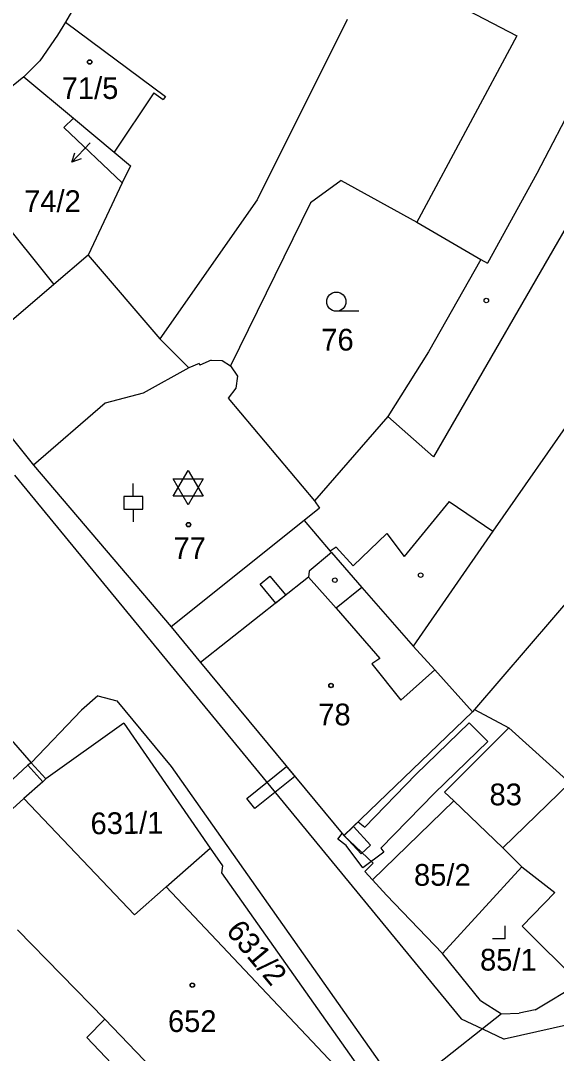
# Model space of a CAD drawing. Extents: x -593183 to -588034, y -1130415 to -1124994.
# Drawn here: x -591020.9 to -590979, y -1128867.8 to -1128787.1 of the extents above; entities that cross this region are included whole.
import ezdxf

# ---------------------------------------------------------------- set-up
doc = ezdxf.new("R2010")
doc.units = 0
for name, color, linetype in [('Vrstva 1', 7, 'Continuous'), ('Vrstva 16', 7, 'Continuous'), ('Vrstva 18', 7, 'Continuous'), ('Vrstva 19', 7, 'Continuous'), ('Vrstva 25', 7, 'Continuous'), ('Vrstva 27', 7, 'Continuous'), ('Vrstva 4', 7, 'Continuous')]:
    doc.layers.add(name, color=color, linetype=linetype)

msp = doc.modelspace()

# ---------------------------------------------------------------- linework, layer by layer
at = {"layer": 'Vrstva 1'}
for p, q in [((-591015.91, -1128784.7), (-591017.38, -1128787.22)), ((-590995.37, -1128787), (-591002.4, -1128801.12)), ((-591017.38, -1128787.22), (-591017.98, -1128788.24)), ((-591017.38, -1128787.22), (-591009.56, -1128793.02)), ((-591017.98, -1128788.24), (-591019.36, -1128790.24)), ((-591019.36, -1128790.24), (-591020.62, -1128791.5)), ((-591020.62, -1128791.5), (-591021.87, -1128792.5)), ((-591020.62, -1128791.5), (-591016.74, -1128794.73)), ((-591010.46, -1128792.73), (-591013.57, -1128797.37)), ((-591010.46, -1128792.73), (-591009.74, -1128793.26)), ((-591009.56, -1128793.02), (-591009.74, -1128793.26)), ((-590977.38, -1128793.01), (-590980.55, -1128799.05)), ((-591016.74, -1128794.73), (-591017.5, -1128795.46)), ((-591016.74, -1128794.73), (-591013.57, -1128797.37)), ((-591017.5, -1128795.46), (-591012.93, -1128799.79)), ((-591013.57, -1128797.37), (-591012.28, -1128798.44)), ((-591012.28, -1128798.44), (-591012.93, -1128799.79)), ((-590980.55, -1128799.05), (-590984.41, -1128806.07)), ((-591012.93, -1128799.79), (-591015.59, -1128805.43)), ((-590995.82, -1128799.59), (-590998.23, -1128801.33)), ((-590995.82, -1128799.59), (-590989.91, -1128802.86)), ((-591002.4, -1128801.12), (-591010.01, -1128811.97)), ((-590998.23, -1128801.33), (-591004.47, -1128814.08)), ((-590989.91, -1128802.86), (-590984.93, -1128805.77)), ((-591015.59, -1128805.43), (-591018.28, -1128807.73)), ((-591015.59, -1128805.43), (-591010.01, -1128811.97)), ((-590984.93, -1128805.77), (-590989.01, -1128812.99)), ((-590984.93, -1128805.77), (-590984.41, -1128806.07)), ((-591018.28, -1128807.73), (-591025.8, -1128814.14)), ((-591010.01, -1128811.97), (-591007.72, -1128814.25)), ((-591005.99, -1128813.64), (-591006.87, -1128814.03)), ((-591005.99, -1128813.64), (-591005.13, -1128813.68)), ((-591005.13, -1128813.68), (-591004.47, -1128814.08)), ((-590989.01, -1128812.99), (-590992.19, -1128818.04)), ((-591007.72, -1128814.25), (-591011.3, -1128816.23)), ((-591006.92, -1128813.91), (-591007.72, -1128814.25)), ((-591006.92, -1128813.91), (-591006.87, -1128814.03)), ((-591004.47, -1128814.08), (-591003.94, -1128814.88)), ((-591003.94, -1128814.88), (-591004.05, -1128815.83)), ((-591004.05, -1128815.83), (-591004.65, -1128816.6)), ((-591011.3, -1128816.23), (-591014.27, -1128817)), ((-591004.65, -1128816.6), (-590997.92, -1128824.64)), ((-591014.27, -1128817), (-591019.87, -1128821.86)), ((-590992.19, -1128818.04), (-590997.92, -1128824.64)), ((-591019.87, -1128821.86), (-591009.11, -1128834.48)), ((-590997.92, -1128824.64), (-590997.52, -1128825.22)), ((-590997.52, -1128825.22), (-590998.72, -1128826.18)), ((-590998.72, -1128826.18), (-591009.11, -1128834.48)), ((-590998.72, -1128826.18), (-590996.69, -1128828.57)), ((-590996.59, -1128828.68), (-590998.34, -1128830.13)), ((-590996.69, -1128828.57), (-590996.59, -1128828.68)), ((-590996.59, -1128828.68), (-590994.21, -1128831.4)), ((-590975.71, -1128829.63), (-590985.42, -1128840.95)), ((-590998.37, -1128830.6), (-591006.81, -1128837.28)), ((-590998.34, -1128830.13), (-590998.37, -1128830.6)), ((-590994.21, -1128831.4), (-590990.21, -1128835.99)), ((-590990.21, -1128835.99), (-590988.52, -1128837.86)), ((-591027.21, -1128837), (-591020.06, -1128845.11)), ((-591006.81, -1128837.28), (-590995.62, -1128850.81)), ((-590988.52, -1128837.86), (-590985.56, -1128841.13)), ((-590985.56, -1128841.13), (-590995.62, -1128850.81)), ((-590985.42, -1128840.95), (-590985.56, -1128841.13)), ((-590985.42, -1128840.95), (-590982.74, -1128842.38)), ((-591012.82, -1128842.02), (-591018.9, -1128846.37)), ((-591012.82, -1128842.02), (-591006.06, -1128851.79)), ((-590982.74, -1128842.38), (-590987.76, -1128847.4)), ((-590982.74, -1128842.38), (-590977.96, -1128846.68)), ((-591020.06, -1128845.11), (-591018.9, -1128846.37)), ((-591019.15, -1128846.6), (-591020.62, -1128847.92)), ((-591018.9, -1128846.37), (-591019.15, -1128846.6)), ((-590977.96, -1128846.68), (-590983.2, -1128851.77)), ((-590987.76, -1128847.4), (-590987.03, -1128848.1)), ((-591020.62, -1128847.92), (-591023.65, -1128850.64)), ((-591020.62, -1128847.92), (-591011.98, -1128857)), ((-590987.03, -1128848.1), (-590993.39, -1128854.26)), ((-590987.03, -1128848.1), (-590983.2, -1128851.77)), ((-591009.49, -1128854.81), (-591006.06, -1128851.79)), ((-591006.06, -1128851.79), (-591005.11, -1128853.17)), ((-590983.2, -1128851.77), (-590981.71, -1128853.24)), ((-591005.11, -1128853.17), (-591005.18, -1128853.72)), ((-590981.71, -1128853.24), (-590987.91, -1128860.03)), ((-590981.71, -1128853.24), (-590979.13, -1128855.25)), ((-591005.18, -1128853.72), (-590992.8, -1128871.26)), ((-591009.49, -1128854.81), (-591011.98, -1128857)), ((-591009.49, -1128854.81), (-590993.32, -1128871.97)), ((-590993.39, -1128854.26), (-590992.28, -1128855.46)), ((-590992.28, -1128855.46), (-590987.91, -1128860.03)), ((-590979.13, -1128855.25), (-590981.68, -1128857.88)), ((-590977.22, -1128862.34), (-590981.68, -1128857.88)), ((-590984.94, -1128863.71), (-590987.91, -1128860.03)), ((-590980.68, -1128864.42), (-590977.22, -1128862.34)), ((-590984.94, -1128863.71), (-590983.3, -1128864.73)), ((-590980.68, -1128864.42), (-590981.92, -1128864.69)), ((-590983.3, -1128864.73), (-590984.8, -1128865.92)), ((-590983.3, -1128864.73), (-590981.92, -1128864.69)), ((-590984.8, -1128865.92), (-590991.4, -1128871.14))]:
    msp.add_line(p, q, dxfattribs=at)
at = {"layer": 'Vrstva 25'}
for p, q in [((-591015.44, -1128796.66), (-591016.866, -1128798.16)), ((-590994.46, -1128809.82), (-590996.21, -1128809.82)), ((-591008.953, -1128824.27), (-591007.78, -1128822.26)), ((-591007.78, -1128822.26), (-591006.607, -1128824.27)), ((-591012.07, -1128824.29), (-591012.07, -1128823.29)), ((-591008.953, -1128822.93), (-591006.607, -1128822.93)), ((-591007.78, -1128824.94), (-591008.953, -1128822.93)), ((-591006.607, -1128822.93), (-591007.78, -1128824.94)), ((-591006.607, -1128824.27), (-591008.953, -1128824.27)), ((-591012.07, -1128825.29), (-591012.07, -1128826.29)), ((-590983.02, -1128858.87), (-590983.02, -1128857.87)), ((-590983.02, -1128858.87), (-590984.02, -1128858.87))]:
    msp.add_line(p, q, dxfattribs=at)
msp.add_lwpolyline([(-591016.141, -1128797.898), (-591016.866, -1128798.16), (-591016.641, -1128797.422)], dxfattribs=at)
msp.add_lwpolyline([(-591012.82, -1128825.29), (-591011.32, -1128825.29), (-591011.32, -1128824.29), (-591012.82, -1128824.29)], close=True, dxfattribs=at)
for centre, radius in [((-591015.48, -1128790.33), 0.175), ((-591015.48, -1128790.33), 0.15), ((-590996.21, -1128809.07), 0.75), ((-590984.49, -1128808.98), 0.175), ((-591007.76, -1128826.5), 0.175), ((-591007.76, -1128826.5), 0.15), ((-590989.62, -1128830.45), 0.175), ((-590996.32, -1128830.84), 0.175), ((-590996.62, -1128839.07), 0.175), ((-590996.62, -1128839.07), 0.15), ((-591007.46, -1128862.5), 0.175), ((-591007.46, -1128862.5), 0.15)]:
    msp.add_circle(centre, radius, dxfattribs=at)
at = {"layer": 'Vrstva 27'}
for p, q in [((-591002.16, -1128831.16), (-591001.4, -1128830.52)), ((-591001.4, -1128830.52), (-591000.15, -1128832.01)), ((-591000.93, -1128832.63), (-591002.16, -1128831.16)), ((-591000.15, -1128832.01), (-591000.93, -1128832.63)), ((-590989.99, -1128846.03), (-590985.82, -1128841.98)), ((-590985.82, -1128841.98), (-590984.38, -1128843.46)), ((-590984.38, -1128843.46), (-590988.53, -1128847.49)), ((-591003.2, -1128847.9), (-591000.09, -1128845.41)), ((-591000.09, -1128845.41), (-590999.45, -1128846.18)), ((-590999.45, -1128846.18), (-591002.58, -1128848.68)), ((-590993.99, -1128850.15), (-590989.99, -1128846.03)), ((-590988.53, -1128847.49), (-590992.72, -1128851.79)), ((-591002.58, -1128848.68), (-591003.2, -1128847.9)), ((-590995.62, -1128850.81), (-590994.51, -1128849.74)), ((-590994.51, -1128849.74), (-590993.99, -1128850.15)), ((-590996.09, -1128851.08), (-590995.75, -1128850.65)), ((-590995.75, -1128850.65), (-590995.62, -1128850.81)), ((-590995.59, -1128850.79), (-590994.87, -1128850.09)), ((-590994.28, -1128852.23), (-590995.59, -1128850.79)), ((-590994.87, -1128850.09), (-590993.54, -1128851.56)), ((-590995.45, -1128851.58), (-590996.09, -1128851.08)), ((-590994.14, -1128853.33), (-590995.45, -1128851.58)), ((-590993.54, -1128851.56), (-590994.28, -1128852.23)), ((-590992.5, -1128852.09), (-590994.14, -1128853.33)), ((-590992.72, -1128851.79), (-590992.5, -1128852.09))]:
    msp.add_line(p, q, dxfattribs=at)
at = {"layer": 'Vrstva 4'}
for p, q in [((-590991.86, -1128783.18), (-590982.1, -1128788.29)), ((-590982.1, -1128788.29), (-590989.75, -1128802.56)), ((-590973.7, -1128795.32), (-590988.62, -1128821.21)), ((-591025.58, -1128798.63), (-591018.28, -1128807.73)), ((-590989.75, -1128802.56), (-590989.91, -1128802.86)), ((-590970.01, -1128806.91), (-590983.98, -1128827.02)), ((-591025.95, -1128814.27), (-591019.87, -1128821.86)), ((-590992.19, -1128818.04), (-590988.62, -1128821.21)), ((-591021.34, -1128822.62), (-590986.45, -1128865.14)), ((-590987.39, -1128824.7), (-590990.91, -1128828.99)), ((-590987.39, -1128824.7), (-590983.98, -1128827.02)), ((-590992.26, -1128827.2), (-590994.9, -1128829.71)), ((-590992.26, -1128827.2), (-590990.91, -1128828.99)), ((-590983.98, -1128827.02), (-590990.21, -1128835.99)), ((-590996.21, -1128828.25), (-590996.69, -1128828.57)), ((-590996.21, -1128828.25), (-590994.9, -1128829.71)), ((-590998.37, -1128830.6), (-590996.23, -1128833.04)), ((-590994.21, -1128831.4), (-590996.23, -1128833.04)), ((-590996.23, -1128833.04), (-590992.8, -1128836.96)), ((-591009.11, -1128834.48), (-591006.81, -1128837.28)), ((-590992.8, -1128836.96), (-590993.44, -1128837.37)), ((-590993.44, -1128837.37), (-590991.18, -1128840.21)), ((-590988.52, -1128837.86), (-590991.18, -1128840.21)), ((-591014.85, -1128839.88), (-591016.12, -1128841)), ((-591014.85, -1128839.88), (-591013.35, -1128840.26)), ((-591013.35, -1128840.26), (-591009.11, -1128845.4)), ((-591016.12, -1128841), (-591020.06, -1128845.11)), ((-591020.06, -1128845.11), (-591020.31, -1128845.29)), ((-591020.31, -1128845.29), (-591024.73, -1128849.42)), ((-591020.31, -1128845.29), (-591019.15, -1128846.6)), ((-591009.11, -1128845.4), (-590991.93, -1128869.79)), ((-590995.62, -1128850.81), (-590993.34, -1128852.97)), ((-590993.34, -1128852.97), (-590993.98, -1128853.61)), ((-590993.98, -1128853.61), (-590993.39, -1128854.26)), ((-591021.12, -1128858.18), (-591014.3, -1128865.15)), ((-591014.3, -1128865.15), (-591015.69, -1128866.6)), ((-591014.3, -1128865.15), (-591010.62, -1128868.99)), ((-590986.45, -1128865.14), (-590984.8, -1128865.92)), ((-590984.8, -1128865.92), (-590983.1, -1128866.73)), ((-590977.99, -1128865.57), (-590983.1, -1128866.73)), ((-591015.69, -1128866.6), (-591012.07, -1128870.4))]:
    msp.add_line(p, q, dxfattribs=at)

# ---------------------------------------------------------------- texts
at = {"layer": 'Vrstva 16'}
msp.add_text('74/2', height=1.7, dxfattribs=at).set_placement((-591020.6, -1128802.06))
at = {"layer": 'Vrstva 18'}
for s, height, p in [('74/2', 0.01, (-591015.44, -1128796.66)), ('76', 1.7, (-590997.38, -1128812.89)), ('83', 1.7, (-590984.24, -1128848.44)), ('85/2', 1.7, (-590990.14, -1128854.73))]:
    msp.add_text(s, height=height, dxfattribs=at).set_placement(p)
for s, rotation, p in [('631/1', 0.61551, (-591015.403, -1128850.707)), ('631/2', 309.75165, (-591004.895, -1128858.302))]:
    msp.add_text(s, height=1.7, rotation=rotation, dxfattribs=at).set_placement(p)
at = {"layer": 'Vrstva 19'}
for s, p in [('71/5', (-591017.66, -1128793.22)), ('77', (-591008.93, -1128829.18)), ('78', (-590997.62, -1128842.19)), ('85/1', (-590984.98, -1128861.36)), ('652', (-591009.36, -1128866.16))]:
    msp.add_text(s, height=1.7, dxfattribs=at).set_placement(p)

doc.saveas('drawing.dxf')
